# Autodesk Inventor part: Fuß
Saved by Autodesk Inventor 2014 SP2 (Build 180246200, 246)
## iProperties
Created: 2015-07
Part Number: Fuß
Material: Generisch
Document SubType Name: Modeling
Designer: e_krauts
Density: 1 g/cm^3
Appearance: Vorgabe
Author: e_krauts
Sending System: SolidWorks 2011
Last Author: e_boekem
Sachnummer: NWS 100-00-02
Erstellt durch: XYZ
Werkstoff: AlCu4PbMg
Einheit: Stck.
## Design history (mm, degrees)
node "Fuß.ipt1"
node "Stirnsenkung für M8 Zylinderschraube mit Innensechskant1"
node "Basis1"
